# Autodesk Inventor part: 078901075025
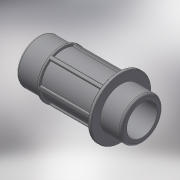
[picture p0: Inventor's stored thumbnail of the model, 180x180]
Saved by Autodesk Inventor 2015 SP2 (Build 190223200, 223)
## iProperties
Created: 2018-02
Part Number: 078901075025
Material: Generic
Description: PLASSON THREADED MALE ADAPTOR 75-2.1/2"
Document SubType Name: Modeling
Designer: KIM
Density: 1 g/cm^3
Appearance: Default
Author: KIM
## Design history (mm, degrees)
derived "078901.ipt"
feature "Solid1::078901.ipt"
tag "TaggingFeature1"
body "Solid1"
other parameters: "d4" = 3.7592, "d14" = 6.01472, "d15" = 3.00736, "d17" = 0, "d20" = 360 deg, "d40" = 29, "d41" = 75.184, "d45" = 82.7024, "d46" = 52.6288, "d47" = 2.9, "d77" = 134, "d78" = 75, "d85" = 0.75184, "d91" = 26.8, "d103" = 30.82, "d105" = 0.75184, "R_" = 75.184, "l_2" = 29, "l_" = 134, "d_" = 75
